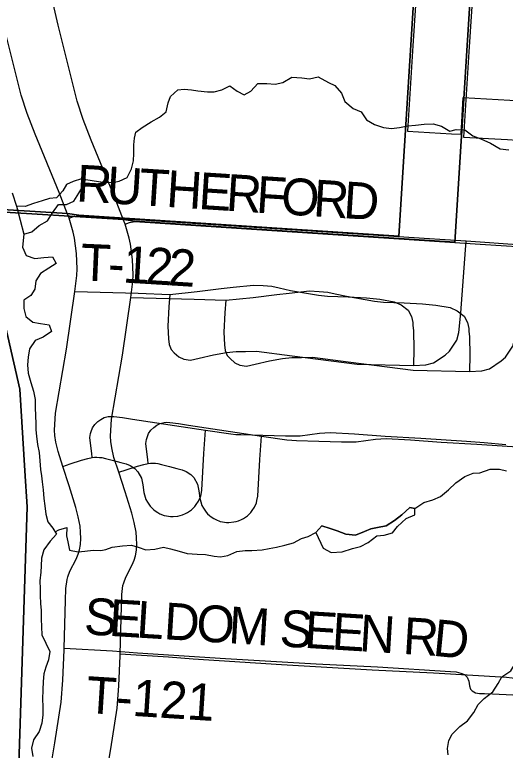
# Model space of a CAD drawing. Extents: x -38.2 to 41.9, y -4 to 24.9.
# Drawn here: x 4.425 to 5.183, y 18.446 to 19.582 of the extents above; entities that cross this region are included whole.
import ezdxf

# ---------------------------------------------------------------- set-up
doc = ezdxf.new("R2010")
doc.units = 0
for name, color, linetype in [('Default', 7, 'Continuous'), ('GM_X_County_Road', 7, 'Continuous'), ('GM_X_Interchange_Ramps', 7, 'Continuous'), ('GM_X_Major_Lake', 7, 'Continuous'), ('GM_X_Major_River', 7, 'Continuous'), ('GM_X_Minor_Lake', 7, 'Continuous'), ('GM_X_Minor_River', 7, 'Continuous'), ('GM_X_State_Location', 7, 'Continuous'), ('GM_X_State_Route', 7, 'Continuous'), ('GM_X_Township_Road', 7, 'Continuous'), ('GM_X_Township_Road_Text', 7, 'Continuous')]:
    doc.layers.add(name, color=color, linetype=linetype)

msp = doc.modelspace()

# ---------------------------------------------------------------- linework, layer by layer
at = {"layer": 'Default'}
msp.add_lwpolyline([(5.048, 19.659), (5.04, 19.534), (5.0316, 19.4023), (5.0997, 19.3984), (5.1145, 19.3975), (5.1178, 19.4543), (5.208, 19.449)], dxfattribs=at)
at = {"layer": 'GM_X_County_Road'}
msp.add_lwpolyline([(5.1345, 19.6498), (5.1265, 19.5248), (5.1181, 19.3931), (5.1862, 19.3892), (5.201, 19.3883), (5.2043, 19.4451), (5.2944, 19.4398), (5.2937, 19.4294), (5.3888, 19.4243), (5.3937, 19.4242), (5.3931, 19.4128), (5.3921, 19.3958), (5.3968, 19.3954), (5.4857, 19.3891), (5.7066, 19.3734), (5.8315, 19.3645)], dxfattribs=at)
at = {"layer": 'GM_X_Interchange_Ramps'}
for points in [[(8.9, 20.9), (5.1243, 20.9), (5.0869, 20.3321), (5.0183, 19.2401), (4.524, 19.2724), (4.5063, 19.2749), (4.2891, 19.2883), (4.3187, 19.1351), (4.3461, 19.0129), (4.3543, 18.8869), (4.3579, 18.8315), (4.3427, 18.3695), (4.3427, 18.2191), (4.3507, 18.0744), (4.3697, 17.9734), (4.4043, 17.861), (4.5071, 17.5648), (4.5129, 17.5446), (4.531, 17.482), (4.5322, 17.4318), (4.517, 17.3994), (4.4957, 17.354), (4.5219, 17.2005)], [(8.9, 20.9), (5.2114, 20.9), (5.1734, 20.3229), (5.1048, 19.2309), (4.6105, 19.2632), (4.5928, 19.2657), (4.3756, 19.2791), (4.4052, 19.1259), (4.4326, 19.0037), (4.4408, 18.8777), (4.4444, 18.8223), (4.4292, 18.3603), (4.4292, 18.2099), (4.4372, 18.0652), (4.4562, 17.9642), (4.4908, 17.8518), (4.5935, 17.5556), (4.5994, 17.5354), (4.6175, 17.4728), (4.6186, 17.4226), (4.6035, 17.3903), (4.5821, 17.3448), (4.6084, 17.1913)], [(4.5219, 17.2005), (4.4957, 17.354), (4.517, 17.3994), (4.5322, 17.4318), (4.531, 17.482), (4.5129, 17.5446), (4.5071, 17.5648), (4.4043, 17.861), (4.3697, 17.9734), (4.3507, 18.0744), (4.3427, 18.2191), (4.3427, 18.3695), (4.3579, 18.8315), (4.3543, 18.8869), (4.3461, 19.0129), (4.3187, 19.1351), (4.2891, 19.2883), (4.5063, 19.2749), (4.524, 19.2724), (5.0183, 19.2401), (5.0869, 20.3321)], [(4.6084, 17.1913), (4.5821, 17.3448), (4.6035, 17.3903), (4.6186, 17.4226), (4.6175, 17.4728), (4.5994, 17.5354), (4.5935, 17.5556), (4.4908, 17.8518), (4.4562, 17.9642), (4.4372, 18.0652), (4.4292, 18.2099), (4.4292, 18.3603), (4.4444, 18.8223), (4.4408, 18.8777), (4.4326, 19.0037), (4.4052, 19.1259), (4.3756, 19.2791), (4.5928, 19.2657), (4.6105, 19.2632), (5.1048, 19.2309), (5.1734, 20.3229)], [(4.5955, 19.2587), (4.593, 19.2651), (4.5801, 19.2985), (4.5432, 19.3884), (4.5306, 19.4203), (4.5214, 19.4485), (4.5029, 19.5226), (4.4923, 19.5658), (4.4777, 19.6287), (4.4699, 19.6591), (4.4632, 19.6807), (4.4483, 19.72), (4.4237, 19.7667), (4.4155, 19.7799), (4.4017, 19.7972), (4.3805, 19.8218), (4.3154, 19.8785)], [(4.6044, 19.1454), (4.6072, 19.1704), (4.6077, 19.1807), (4.6071, 19.2041), (4.6038, 19.2279), (4.6018, 19.237), (4.5955, 19.2587)], [(4.5686, 18.4211), (4.5733, 18.4486), (4.5797, 18.4883), (4.583, 18.5113), (4.5857, 18.5456), (4.5876, 18.5923), (4.5877, 18.595), (4.5898, 18.6682), (4.5905, 18.687), (4.5922, 18.7007), (4.5933, 18.7051), (4.5965, 18.7138), (4.6062, 18.7324), (4.6094, 18.74), (4.6116, 18.7466), (4.613, 18.7551), (4.6134, 18.7643), (4.6132, 18.7741), (4.6124, 18.783), (4.6096, 18.7978), (4.6057, 18.8122), (4.5953, 18.8452), (4.5856, 18.8755), (4.5783, 18.8986), (4.5747, 18.9131), (4.5733, 18.9232), (4.5731, 18.9313), (4.5745, 18.9577), (4.5912, 19.0564), (4.6044, 19.1454)]]:
    msp.add_lwpolyline(points, dxfattribs=at)
at = {"layer": 'GM_X_Major_Lake'}
msp.add_line((4.4277, 19.2864), (4.4388, 19.243), dxfattribs=at)
for points in [[(4.421, 19.3069), (4.4277, 19.2864)], [(4.4388, 19.243), (4.4369, 19.2231), (4.4426, 19.2105), (4.4562, 19.2059), (4.4699, 19.207), (4.4832, 19.2084), (4.4892, 19.1982), (4.4774, 19.191), (4.4649, 19.1824), (4.4576, 19.171), (4.456, 19.1585), (4.4499, 19.1483), (4.4392, 19.1412), (4.4392, 19.1286), (4.4422, 19.1161), (4.4531, 19.1074), (4.4649, 19.1054), (4.4782, 19.1034), (4.4815, 19.0928), (4.469, 19.0841), (4.4564, 19.0793), (4.448, 19.0664), (4.4457, 19.0535), (4.4449, 19.0414), (4.4456, 19.0285), (4.45, 19.0141), (4.4542, 19.0008), (4.4564, 18.9879), (4.4567, 18.9758), (4.457, 18.9625), (4.4574, 18.9507), (4.4577, 18.9409), (4.4584, 18.9314), (4.4603, 18.9185), (4.4625, 18.9059), (4.4639, 18.893), (4.4646, 18.8801), (4.4661, 18.8703), (4.4672, 18.8608), (4.4687, 18.8483), (4.4698, 18.835), (4.4712, 18.824), (4.4731, 18.8111), (4.4761, 18.7993), (4.484, 18.7894), (4.4896, 18.7799), (4.4797, 18.7693), (4.4698, 18.7557), (4.4663, 18.7428), (4.4659, 18.7311), (4.4651, 18.7212), (4.4635, 18.7079), (4.4642, 18.6954), (4.4645, 18.6859), (4.4649, 18.6723), (4.4656, 18.6624), (4.4659, 18.6495), (4.4662, 18.637), (4.4669, 18.6245), (4.473, 18.6115), (4.479, 18.5986), (4.477, 18.5861), (4.4728, 18.5747), (4.4697, 18.5645), (4.4689, 18.5524), (4.4685, 18.5398), (4.468, 18.5254), (4.4684, 18.5137), (4.4683, 18.5011), (4.4667, 18.4882), (4.4629, 18.4754), (4.4541, 18.4625), (4.4506, 18.4496), (4.4528, 18.4367)]]:
    msp.add_lwpolyline(points, dxfattribs=at)
at = {"layer": 'GM_X_Major_River'}
msp.add_line((4.4277, 19.2864), (4.4388, 19.243), dxfattribs=at)
for points in [[(4.4388, 19.243), (4.4514, 19.2466), (4.4628, 19.2564), (4.4757, 19.2636), (4.4834, 19.2764), (4.4925, 19.2893), (4.505, 19.2893), (4.5164, 19.2942), (4.5241, 19.3066), (4.5309, 19.318), (4.5283, 19.3286), (4.515, 19.3245), (4.5051, 19.32), (4.4994, 19.3101), (4.4895, 19.2995), (4.4789, 19.2984), (4.4671, 19.2947), (4.4538, 19.2905), (4.4409, 19.286), (4.4277, 19.2864)], [(4.421, 19.3069), (4.4277, 19.2864)], [(4.4388, 19.243), (4.4369, 19.2231), (4.4426, 19.2105), (4.4562, 19.2059), (4.4699, 19.207), (4.4832, 19.2084), (4.4892, 19.1982), (4.4774, 19.191), (4.4649, 19.1824), (4.4576, 19.171), (4.456, 19.1585), (4.4499, 19.1483), (4.4392, 19.1412), (4.4392, 19.1286), (4.4422, 19.1161), (4.4531, 19.1074), (4.4649, 19.1054), (4.4782, 19.1034), (4.4815, 19.0928), (4.469, 19.0841), (4.4564, 19.0793), (4.448, 19.0664), (4.4457, 19.0535), (4.4449, 19.0414), (4.4456, 19.0285), (4.45, 19.0141), (4.4542, 19.0008), (4.4564, 18.9879), (4.4567, 18.9758), (4.457, 18.9625), (4.4574, 18.9507), (4.4577, 18.9409), (4.4584, 18.9314), (4.4603, 18.9185), (4.4625, 18.9059), (4.4639, 18.893), (4.4646, 18.8801), (4.4661, 18.8703), (4.4672, 18.8608), (4.4687, 18.8483), (4.4698, 18.835), (4.4712, 18.824), (4.4731, 18.8111), (4.4761, 18.7993), (4.484, 18.7894), (4.4896, 18.7799), (4.4797, 18.7693), (4.4698, 18.7557), (4.4663, 18.7428), (4.4659, 18.7311), (4.4651, 18.7212), (4.4635, 18.7079), (4.4642, 18.6954), (4.4645, 18.6859), (4.4649, 18.6723), (4.4656, 18.6624), (4.4659, 18.6495), (4.4662, 18.637), (4.4669, 18.6245), (4.473, 18.6115), (4.479, 18.5986), (4.477, 18.5861), (4.4728, 18.5747), (4.4697, 18.5645), (4.4689, 18.5524), (4.4685, 18.5398), (4.468, 18.5254), (4.4684, 18.5137), (4.4683, 18.5011), (4.4667, 18.4882), (4.4629, 18.4754), (4.4541, 18.4625), (4.4506, 18.4496), (4.4528, 18.4367)]]:
    msp.add_lwpolyline(points, dxfattribs=at)
at = {"layer": 'GM_X_Minor_Lake'}
for points in [[(5.043, 18.8196), (5.0351, 18.8211), (5.023, 18.8101), (5.0116, 18.801), (4.9987, 18.7927), (4.9855, 18.7901), (4.9753, 18.7882), (4.9654, 18.784), (4.9514, 18.7783), (4.9363, 18.7802), (4.923, 18.7851), (4.9124, 18.7886), (4.8996, 18.7931), (4.8901, 18.7825)], [(4.8901, 18.7825), (4.9015, 18.7582), (4.9136, 18.7518), (4.931, 18.7529), (4.9469, 18.7578), (4.959, 18.7612), (4.9711, 18.7673), (4.9844, 18.7775), (4.9957, 18.7787), (5.0086, 18.7821), (5.0161, 18.7919), (5.0298, 18.8044), (5.043, 18.8101), (5.043, 18.8196)]]:
    msp.add_lwpolyline(points, dxfattribs=at)
at = {"layer": 'GM_X_Minor_River'}
for points in [[(4.5613, 19.3235), (4.5641, 19.3235), (4.5766, 19.3231), (4.5864, 19.325), (4.5985, 19.331), (4.6053, 19.3439), (4.6083, 19.3564), (4.6091, 19.3678), (4.6091, 19.3814), (4.6098, 19.3913), (4.6121, 19.4007), (4.622, 19.4079), (4.6356, 19.4166), (4.6484, 19.4238), (4.6587, 19.4322), (4.6621, 19.4458), (4.6655, 19.456), (4.6768, 19.4659), (4.6867, 19.4674), (4.698, 19.4662), (4.7079, 19.4644), (4.7226, 19.4632), (4.7332, 19.4632), (4.7449, 19.4659), (4.7574, 19.4723), (4.7684, 19.464), (4.7794, 19.4586), (4.7896, 19.4639), (4.8006, 19.4757), (4.8146, 19.4757), (4.8274, 19.4749), (4.8392, 19.4772), (4.8532, 19.4855), (4.8687, 19.4848), (4.8801, 19.4829), (4.8937, 19.4863), (4.9096, 19.4772), (4.9194, 19.473), (4.9296, 19.4612), (4.9349, 19.448), (4.9478, 19.4374), (4.9603, 19.4321), (4.9683, 19.4196), (4.9807, 19.4127), (4.9947, 19.4082), (5.0072, 19.4063), (5.0193, 19.4082), (5.0322, 19.4105), (5.0439, 19.4116), (5.0576, 19.4131), (5.0716, 19.4135), (5.0841, 19.4101), (5.0969, 19.4025), (5.1068, 19.4051), (5.1204, 19.4044), (5.1325, 19.3953), (5.145, 19.3907), (5.1598, 19.3839), (5.1749, 19.3752), (5.1885, 19.3736)], [(4.5283, 19.3286), (4.5613, 19.3235)], [(4.5578, 18.755), (4.5658, 18.7564), (4.5756, 18.7599), (4.5915, 18.7621), (4.6051, 18.7629), (4.6157, 18.7598), (4.6275, 18.7557), (4.6415, 18.7568), (4.6547, 18.7598), (4.6657, 18.7576), (4.6789, 18.7538), (4.6914, 18.75), (4.7066, 18.7492), (4.7198, 18.7484), (4.7331, 18.7462), (4.7429, 18.745), (4.7543, 18.7473), (4.7683, 18.753), (4.7808, 18.7549), (4.7914, 18.7549), (4.8072, 18.756), (4.8178, 18.7579), (4.8292, 18.7598), (4.8421, 18.7628), (4.8557, 18.7666), (4.8682, 18.7734), (4.8784, 18.7764), (4.8901, 18.7825), (4.8996, 18.7931), (4.9124, 18.7886), (4.923, 18.7851), (4.9363, 18.7802), (4.9514, 18.7783), (4.9654, 18.784), (4.9753, 18.7882), (4.9855, 18.7901), (4.9987, 18.7927), (5.0116, 18.801), (5.023, 18.8101), (5.0351, 18.8211), (5.043, 18.8196), (5.057, 18.8287), (5.0706, 18.8329), (5.0827, 18.8382), (5.0952, 18.8484), (5.1066, 18.8594), (5.1202, 18.8692), (5.1331, 18.8742), (5.1433, 18.8749), (5.1596, 18.8802), (5.1739, 18.8802), (5.1845, 18.8776)], [(4.4873, 18.7838), (4.4933, 18.7867), (4.5055, 18.7905), (4.5047, 18.7776), (4.5069, 18.7681), (4.5096, 18.7552), (4.5232, 18.7529), (4.5331, 18.7536), (4.546, 18.7555), (4.5578, 18.755)], [(5.0943, 18.4392), (5.0935, 18.4491), (5.0958, 18.4616), (5.1007, 18.4711), (5.1128, 18.4828), (5.1245, 18.4919), (5.1344, 18.5044), (5.1408, 18.517), (5.1502, 18.5264), (5.1635, 18.5363), (5.1718, 18.5492), (5.1775, 18.5598), (5.1911, 18.5689), (5.1983, 18.581), (5.2051, 18.5928), (5.2115, 18.6072), (5.2232, 18.6193), (5.2316, 18.6322), (5.235, 18.6417), (5.2372, 18.6512), (5.244, 18.6637), (5.2508, 18.6773), (5.2584, 18.6887)]]:
    msp.add_lwpolyline(points, dxfattribs=at)
at = {"layer": 'GM_X_State_Location'}
msp.add_line((4.7513, 19.1411), (4.7493, 19.1217), dxfattribs=at)
for points in [[(4.5955, 19.2587), (4.6022, 19.2612), (4.6107, 19.2626), (5.105, 19.2304), (5.1439, 19.2278)], [(4.9398, 19.0463), (5.0406, 19.0332), (5.1274, 19.0311), (5.1467, 19.0324), (5.1583, 19.0353), (5.1763, 19.0474), (5.1829, 19.0532), (5.1942, 19.0703), (5.1975, 19.0824), (5.2004, 19.1128), (5.2089, 19.2236)], [(5.1439, 19.2278), (5.2089, 19.2236), (5.3807, 19.2115), (5.5662, 19.1987), (5.8237, 19.1807), (6.0278, 19.1668), (6.0922, 19.1623), (6.101, 19.1629), (6.1331, 19.1605)], [(4.6044, 19.1454), (4.7021, 19.1428), (4.7513, 19.1411), (4.7931, 19.1456), (4.8301, 19.1502), (4.8488, 19.1522)], [(4.8488, 19.1522), (4.8802, 19.1555), (4.8952, 19.1548), (4.9085, 19.1537), (4.92, 19.1513), (4.9377, 19.1473), (4.9809, 19.14), (4.9946, 19.1384), (5.0264, 19.1372), (5.055, 19.1355), (5.0753, 19.1338), (5.0978, 19.1298), (5.1086, 19.1249), (5.119, 19.1166), (5.1243, 19.1071), (5.1267, 19.0977), (5.1267, 19.0935), (5.1274, 19.0848), (5.1278, 19.0566), (5.1274, 19.0311)], [(4.7493, 19.1217), (4.7481, 19.0921), (4.7489, 19.0723), (4.7498, 19.0638)], [(4.7498, 19.0638), (4.7533, 19.0559), (4.758, 19.051), (4.7651, 19.0446), (4.7726, 19.041), (4.7829, 19.0395), (4.7964, 19.0425)], [(4.7964, 19.0425), (4.8187, 19.0475), (4.8388, 19.0513), (4.8532, 19.0529), (4.868, 19.0529), (4.8851, 19.0535), (4.9398, 19.0463)], [(4.631, 18.8891), (4.6304, 18.8954), (4.6279, 18.9155), (4.6277, 18.9201), (4.6284, 18.9263), (4.6293, 18.9294), (4.6318, 18.9352), (4.6353, 18.9404), (4.6398, 18.9449), (4.6443, 18.9481), (4.6497, 18.9508), (4.6556, 18.9524), (4.6587, 18.9528), (4.6648, 18.9526), (4.6778, 18.9507), (4.6933, 18.9483), (4.806, 18.9314), (4.8451, 18.9257), (4.8528, 18.925), (4.8604, 18.9245), (4.8947, 18.9236), (4.9295, 18.9226), (4.9448, 18.9225), (4.9523, 18.9227), (4.9823, 18.9268), (4.9988, 18.9279), (5.0365, 18.9256), (5.0837, 18.922), (5.1386, 18.9189), (5.2093, 18.9142)], [(4.5856, 18.8755), (4.5969, 18.8794), (4.6145, 18.8849), (4.6242, 18.8877), (4.631, 18.8891), (4.6347, 18.8895), (4.6385, 18.8896), (4.6423, 18.8895), (4.6461, 18.889), (4.6515, 18.8878), (4.6642, 18.8844), (4.6755, 18.8813), (4.6835, 18.8792), (4.6898, 18.8768), (4.6969, 18.872), (4.7015, 18.8673), (4.7072, 18.8572), (4.7096, 18.8469), (4.7107, 18.8354), (4.7142, 18.8245), (4.7164, 18.8202), (4.7184, 18.8171), (4.7206, 18.8142), (4.723, 18.8115), (4.7257, 18.8089), (4.7286, 18.8067), (4.7325, 18.8041), (4.7357, 18.8024), (4.7425, 18.7998), (4.746, 18.799), (4.7523, 18.7982), (4.7559, 18.7981), (4.7633, 18.7988), (4.7669, 18.7996), (4.7704, 18.8007), (4.7753, 18.8027), (4.7785, 18.8044), (4.7844, 18.8085), (4.7896, 18.8136), (4.7918, 18.8164), (4.7953, 18.8218), (4.7982, 18.8284), (4.7992, 18.8318), (4.8004, 18.8389), (4.8037, 18.8952), (4.806, 18.9314)], [(4.5877, 18.595), (4.6625, 18.5905), (4.7008, 18.5876), (4.8372, 18.579), (4.977, 18.5707), (5.0721, 18.5657), (5.1846, 18.559), (5.1932, 18.5583), (5.2008, 18.5564), (5.2061, 18.5541), (5.2102, 18.5499), (5.2129, 18.5436), (5.2142, 18.5367), (5.2153, 18.5317), (5.2179, 18.5288), (5.2233, 18.5258), (5.2293, 18.5247), (5.2372, 18.5246), (5.2495, 18.5241), (5.3228, 18.5206), (5.3806, 18.5185), (5.5802, 18.5073), (5.6407, 18.5041), (5.8731, 18.4915)]]:
    msp.add_lwpolyline(points, dxfattribs=at)
at = {"layer": 'GM_X_State_Route'}
for points in [[(4.509, 19.2678), (4.5065, 19.2743), (4.4936, 19.3077), (4.4567, 19.3976), (4.4441, 19.4295), (4.4349, 19.4577), (4.4165, 19.5318), (4.4058, 19.575), (4.3912, 19.6379), (4.3834, 19.6683), (4.3767, 19.6899), (4.3618, 19.7292), (4.3373, 19.7759), (4.329, 19.7891), (4.3152, 19.8064), (4.2941, 19.831), (4.2289, 19.8876)], [(4.5179, 19.1546), (4.5208, 19.1796), (4.5212, 19.1899), (4.5206, 19.2133), (4.5173, 19.2371), (4.5154, 19.2461), (4.509, 19.2678)], [(4.4822, 18.4302), (4.4868, 18.4578), (4.4932, 18.4975), (4.4965, 18.5205), (4.4993, 18.5548), (4.5011, 18.6015), (4.5012, 18.6042), (4.5033, 18.6774), (4.504, 18.6962), (4.5057, 18.7099), (4.5069, 18.7143), (4.5101, 18.723), (4.5197, 18.7416), (4.5229, 18.7492), (4.5251, 18.7558), (4.5266, 18.7643), (4.527, 18.7735), (4.5268, 18.7833), (4.5259, 18.7922), (4.5232, 18.807), (4.5192, 18.8214), (4.5089, 18.8544), (4.4991, 18.8847), (4.4919, 18.9078), (4.4882, 18.9223), (4.4868, 18.9324), (4.4866, 18.9405), (4.488, 18.9669), (4.5047, 19.0655), (4.5179, 19.1546)]]:
    msp.add_lwpolyline(points, dxfattribs=at)
at = {"layer": 'GM_X_Township_Road'}
msp.add_line((4.6648, 19.1503), (4.6628, 19.1309), dxfattribs=at)
for points in [[(4.509, 19.2678), (4.5157, 19.2704), (4.5242, 19.2718), (5.0185, 19.2396), (5.0575, 19.237)], [(4.8533, 19.0555), (4.9541, 19.0424), (5.0409, 19.0403), (5.0602, 19.0415), (5.0719, 19.0445), (5.0898, 19.0565), (5.0964, 19.0624), (5.1077, 19.0795), (5.111, 19.0915), (5.1139, 19.122), (5.1224, 19.2328)], [(5.0575, 19.237), (5.1224, 19.2328), (5.2942, 19.2207), (5.4797, 19.2079), (5.7373, 19.1899), (5.9413, 19.176), (6.0057, 19.1715), (6.0145, 19.1721), (6.0466, 19.1697)], [(4.7623, 19.1614), (4.7938, 19.1647), (4.8087, 19.164), (4.822, 19.1629), (4.8335, 19.1605), (4.8512, 19.1564), (4.8944, 19.1491), (4.9081, 19.1476), (4.9399, 19.1463), (4.9685, 19.1447), (4.9889, 19.143), (5.0113, 19.139), (5.0221, 19.1341), (5.0326, 19.1258), (5.0378, 19.1163), (5.0402, 19.1069), (5.0402, 19.1027), (5.0409, 19.094), (5.0413, 19.0658), (5.0409, 19.0403)], [(4.5179, 19.1546), (4.6156, 19.152), (4.6648, 19.1503), (4.7066, 19.1547), (4.7436, 19.1594), (4.7623, 19.1614)], [(4.6628, 19.1309), (4.6616, 19.1013), (4.6624, 19.0815), (4.6633, 19.073)], [(4.6633, 19.073), (4.6668, 19.0651), (4.6715, 19.0601), (4.6786, 19.0538), (4.6862, 19.0501), (4.6964, 19.0487), (4.71, 19.0517)], [(4.71, 19.0517), (4.7322, 19.0567), (4.7523, 19.0605), (4.7668, 19.0621), (4.7815, 19.0621), (4.7986, 19.0627), (4.8533, 19.0555)], [(4.5445, 18.8983), (4.5439, 18.9046), (4.5414, 18.9247), (4.5412, 18.9292), (4.542, 18.9355), (4.5428, 18.9386), (4.5453, 18.9444), (4.5489, 18.9496), (4.5534, 18.9541), (4.5578, 18.9573), (4.5633, 18.96), (4.5692, 18.9616), (4.5722, 18.9619), (4.5783, 18.9617), (4.5914, 18.9599), (4.6068, 18.9574), (4.7195, 18.9406), (4.7587, 18.9349), (4.7663, 18.9341), (4.774, 18.9337), (4.8082, 18.9328), (4.843, 18.9318), (4.8583, 18.9316), (4.8659, 18.9319), (4.8958, 18.936), (4.9123, 18.9371), (4.95, 18.9348), (4.9972, 18.9312), (5.0521, 18.9281), (5.1229, 18.9234), (5.1503, 18.9213), (5.1837, 18.9185)], [(4.4991, 18.8847), (4.5104, 18.8886), (4.528, 18.8941), (4.5378, 18.8968), (4.5445, 18.8983), (4.5482, 18.8987), (4.552, 18.8988), (4.5558, 18.8986), (4.5596, 18.8982), (4.565, 18.897), (4.5777, 18.8936), (4.5891, 18.8905), (4.5971, 18.8884), (4.6033, 18.886), (4.6104, 18.8812), (4.615, 18.8765), (4.6208, 18.8664), (4.6231, 18.8561), (4.6242, 18.8446), (4.6277, 18.8337), (4.6299, 18.8294), (4.6319, 18.8263), (4.6341, 18.8234), (4.6366, 18.8206), (4.6392, 18.8181), (4.6421, 18.8158), (4.646, 18.8133), (4.6492, 18.8116), (4.656, 18.809), (4.6595, 18.8082), (4.6658, 18.8074), (4.6695, 18.8073), (4.6768, 18.808), (4.6804, 18.8088), (4.6839, 18.8099), (4.6888, 18.8119), (4.692, 18.8136), (4.6979, 18.8177), (4.7031, 18.8228), (4.7054, 18.8256), (4.7088, 18.831), (4.7117, 18.8375), (4.7128, 18.841), (4.7139, 18.8481), (4.7172, 18.9044), (4.7195, 18.9406)], [(4.5012, 18.6042), (4.576, 18.5997), (4.6144, 18.5968), (4.7507, 18.5882), (4.8905, 18.5799), (4.9856, 18.5749), (5.0981, 18.5682), (5.1068, 18.5675), (5.1143, 18.5656), (5.1196, 18.5633), (5.1237, 18.5591), (5.1265, 18.5528), (5.1277, 18.5459), (5.1288, 18.5409), (5.1314, 18.5379), (5.1368, 18.535), (5.1429, 18.5339), (5.1507, 18.5338), (5.163, 18.5333), (5.2363, 18.5298)]]:
    msp.add_lwpolyline(points, dxfattribs=at)

# ---------------------------------------------------------------- texts
at = {"layer": 'GM_X_Township_Road_Text'}
for s, height, rotation, p in [('R', 0.0568, 356.7745, (4.5192, 19.294)), ('U', 0.0568, 356.3621, (4.5657, 19.2913)), ('T', 0.0568, 356.3591, (4.6156, 19.2882)), ('H', 0.0568, 356.3566, (4.658, 19.2855)), ('E', 0.0568, 356.3567, (4.7079, 19.2823)), ('R', 0.0568, 356.3561, (4.7503, 19.2796)), ('F', 0.0568, 356.3575, (4.7969, 19.2766)), ('O', 0.0568, 356.3585, (4.8351, 19.2742)), ('R', 0.0568, 356.3592, (4.885, 19.271)), ('D', 0.0568, 356.3585, (4.9316, 19.2681)), ('T', 0.0568, 357.4793, (4.5256, 19.1719)), ('1', 0.0568, 356.5581, (4.5911, 19.1687)), ('2', 0.0568, 356.5373, (4.6261, 19.1666)), ('2', 0.0568, 356.5217, (4.661, 19.1644)), ('-', 0.0568, 356.6416, (4.5679, 19.17)), ('S', 0.0568, 356.4818, (4.5312, 18.6255)), ('E', 0.0568, 356.4815, (4.5695, 18.6231)), ('L', 0.0568, 356.4793, (4.6119, 18.6205)), ('D', 0.0568, 356.4814, (4.6543, 18.6179)), ('O', 0.0568, 356.4825, (4.7042, 18.6149)), ('M', 0.0568, 356.48, (4.7541, 18.6118)), ('S', 0.0568, 356.4812, (4.8331, 18.6069)), ('E', 0.0568, 356.4826, (4.8714, 18.6046)), ('E', 0.0568, 356.4835, (4.9138, 18.602)), ('N', 0.0568, 356.4789, (4.9562, 18.5994)), ('R', 0.0568, 356.4812, (5.0236, 18.5952)), ('D', 0.0568, 354.3847, (5.0696, 18.5924)), ('T-121', 0.05682, 356.3521, (4.534, 18.5041))]:
    msp.add_text(s, height=height, rotation=rotation, dxfattribs=at).set_placement(p)

doc.saveas('drawing.dxf')
